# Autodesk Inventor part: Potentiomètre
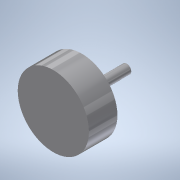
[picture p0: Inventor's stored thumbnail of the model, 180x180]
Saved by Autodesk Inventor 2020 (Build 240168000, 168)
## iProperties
Created: 2002-01
Part Number: Potentiomètre
Material: Aluminium 6061
Document SubType Name: Modélisation
Designer: Philippe
Mass: 0.869994 g
Surface Area: 3.08203 cm^2
Volume: 0.32222 cm^3
Density: 2.7 g/cm^3
Appearance: AI2-O3 (poli)
Shininess: 59.0
Angle Display Precision: 2
Document Length Units: 11269
Document Angle Units: 11279
Document Time Units: 11290
Document Mass Units: 11283
Document Length Units Precision: 3
Document Angle Units Precision: 2
Density: 0.0
Volumn: 0.0
Area: 0.0
PropertySet Name: Model Information
Control State: 0
Master: False
Checked Out: False
Author: Philippe
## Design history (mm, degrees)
sketch "Esquisse1"
  geometry: L1 (0, 0)-(5, 0); L2 (5, 0)-(5, 4); L3 (5, 4)-(0.65, 4); L4 (0.65, 4)-(0.65, 10.3); L5 (0.65, 10.3)-(0, 10.3); L6 (0, 10.3)-(0, 0)
  constraints: 12 end point, 4 parallel, 1 horizontal, 1 perpendicular, 1 other
  dimensions: "d0" = 10 diameter of L2 L6; "d1" = 4 distance between parallel lines of L3 L1; "d2" = 1.3 diameter of L4 L6; "d3" = 6.3 distance of L3.end L4.end
revolve "Révolution1" sketch "Esquisse1" stored, may be unused: angle "d4" = 90 deg
sketch "Esquisse2"
  geometry: L1 (-0.548, 0.35)-(0.548, 0.35); A1 r 0.65 centre (0, 0) between (-0.548, 0.35) and (0.548, 0.35) reference; A2 r 0.65 centre (0, 0) between (-0.548, 0.35) and (0.548, 0.35) reference
  constraints: 4 point on circle, 2 end point, 1 horizontal
  dimensions: "d5" = 0.35 distance from line of L1 A1.centre
extrude "Extrusion1" cut sketch "Esquisse2" distance "d6" = 1.3; taper "d7" = 0 deg
node "Solide1"
node "Corps solides"
node "Corps surfaciques"
